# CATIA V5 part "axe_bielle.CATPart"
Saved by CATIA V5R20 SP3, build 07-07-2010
Part number: axe_bielle
Bounding box of the stored display mesh (mm): x -5 to 2, y -1 to 1, z -1 to 1
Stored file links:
  C:\Documents and Settings\Propriétaire\Mes documents\IFMA\COURS\PROJ IAO\CATIA\axe_bielle.CATPart
  C:\Documents and Settings\Propriétaire\Mes documents\IFMA\COURS\PROJ IAO\CATIA\dwalter.CATProduct
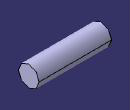
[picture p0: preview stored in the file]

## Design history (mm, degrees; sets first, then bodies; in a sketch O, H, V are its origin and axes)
Set1
  Plane1: linked copy from another document
Body1 (main body)
  Sketch1 on Plane1, origin (0, 0, 0), H (0, 1, 0), V (0, 0, 1)
    circle A1 centre (0, 0) radius 1
    point P1 (-1, 0)
    radius A1 = 1
    coincidence: A1 P1, P1 H
  Pad1: profile Sketch1, direction (-1, 0, 0), length 5
  Pad2: profile start face of Pad1, direction along Plane1, length 2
